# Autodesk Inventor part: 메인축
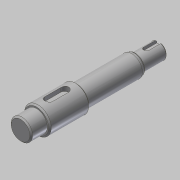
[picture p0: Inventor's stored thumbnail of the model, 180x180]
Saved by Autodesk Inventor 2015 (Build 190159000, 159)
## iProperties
Created: 2019-03
Part Number: 메인축
Material: 강철, 연강
Document SubType Name: Modeling
Designer: mduedu
Density: 1 g/cm^3
Appearance: 강철
Author: mduedu
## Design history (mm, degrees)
sketch "스케치1"
  geometry: L1 (0, 0)-(12, 0); L2 (12, 0)-(12, 8); L3 (12, 8)-(0, 8); L4 (0, 8)-(0, 0); L5 (12, 0)-(42, 0); L6 (42, 0)-(42, 10); L7 (42, 10)-(12, 10); L8 (12, 10)-(12, 0); L9 (42, 0)-(86, 0); L10 (86, 0)-(86, 8); L11 (86, 8)-(42, 8); L12 (42, 8)-(42, 0); L13 (86, 0)-(104, 0); L14 (104, 0)-(104, 6); L15 (104, 6)-(86, 6); L16 (86, 6)-(86, 0)
  constraints: 32 end point, 8 parallel, 4 horizontal, 4 perpendicular
  dimensions: "d0" = 16 diameter of L3 L1; "d2" = 20 diameter of L7 L5; "d3" = 16 diameter of L11 L9; "d4" = 12 diameter of L15 L13; "d5" = 12 distance of L2.end L3.end; "d6" = 30 distance of L6.end L7.end; "d7" = 86 distance between parallel lines of L10 L4; "d8" = 104 distance between parallel lines of L14 L4
revolve "회전1" sketch "스케치1" stored, may be unused: angle "d9" = 90 deg
node "작업 평면1"
sketch "스케치2" dims "d10" = 18
  geometry: L1 (6, -3)-(-6, -3); L2 (-6, -3)-(-6, 3); L3 (-6, 3)-(6, 3); L4 (6, 3)-(6, -3); L5 (15, 10)-(15, -10) reference; 3 further points
  constraints: 8 end point, 2 midpoint, 2 parallel, 2 vertical alignment, 1 horizontal, 1 horizontal alignment, 1 perpendicular, 4 other
  dimensions: "d12" = 6 distance between parallel lines of L3 L1; "d13" = 6 dimension on L5
extrude "돌출1" cut sketch "스케치2" distance "d14" = 3.5; taper "d15" = 0 deg
node "작업 평면2"
sketch "스케치3"
  geometry: L1 (-9, 6)-(-9, -6) reference; L2 (1, -2)-(-9, -2); L3 (1, 2)-(-9, 2); A1 r 2 centre (1, 0) between (1, -2) and (1, 2); 2 further points
  constraints: 4 end point, 2 point on circle, 2 point on line, 2 tangent, 1 centre point, 1 horizontal alignment, 1 midpoint, 1 parallel, 1 perpendicular
  dimensions: "d16" = 12 dimension on A1 L1; "d17" = 4 distance between parallel lines of L3 L2
extrude "돌출2" cut sketch "스케치3" distance "d18" = 2.5; taper "d19" = 0 deg
chamfer "모따기1" distance "d20" = 1; stored, may be unused: second distance "d21" = 2, angle "d22" = 45 deg
chamfer "모따기2" distance "d23" = 1; stored, may be unused: second distance "d24" = 2, angle "d25" = 45 deg
chamfer "모따기3" distance "d26" = 1.73; stored, may be unused: second distance "d27" = 2, angle "d28" = 30 deg
fillet "모깎기2" dims "d31" = 0.5, "d32" = 4
node "솔리드1"
